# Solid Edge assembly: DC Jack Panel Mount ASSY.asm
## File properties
Author: morva
Template: iso metric assembly.asm
Last saved by: morva
Revision: 1
Application: Solid Edge
Username: morva
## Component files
DC Jack Panel Mount Base_0.par
DC Jack Panel Mount Nut_0.par
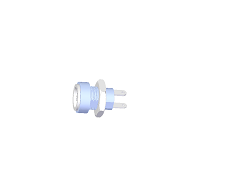
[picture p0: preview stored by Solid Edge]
